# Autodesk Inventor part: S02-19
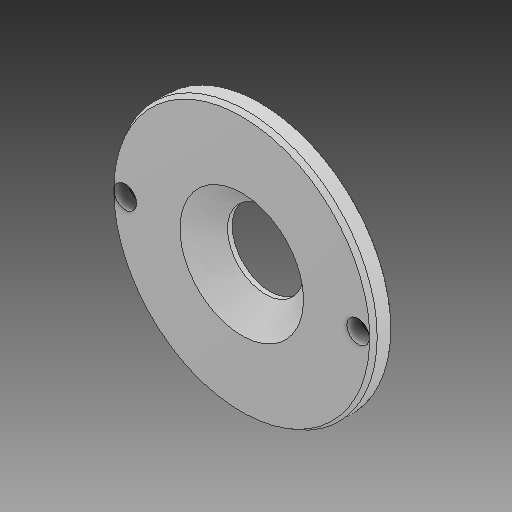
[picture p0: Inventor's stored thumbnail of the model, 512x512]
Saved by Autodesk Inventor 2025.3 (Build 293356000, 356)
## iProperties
Created: 2025-04
Part Number: S02-19
Material: Všeobecné
Document SubType Name: Modeling
Designer: Patrik
Density: 1 g/cm^3
Appearance: Výchozí
Description: Středící kroužek s osazením a konickým otvorem, s vývrty pro šrouby
Stock Number: E 1362_110_90_30x12
Mass: 84.3561 g
Surface Area: 219.333 cm^2
Volume: 84.3561 cm^3
User Status: 1.1730
Sending System: KiM GmbH
Major Version: 4.0
Minor Version: 0.0
Format Version: 0.0
Product Id: KiM GmbH
Hersteller: Meusburger
Material: 1.0503 (1.1730)
Bestellnummer: E 1362/110/90/30x12
Teilenummer: E 1362/110/90/30x12
Beschreibung: Zentrierflansch mit Ansatz und Bohrung konisch, Schraubenbohrungen _ Locating ring with neck, tapered bore and screw holes
cc_prop_force_one_body: 1
Author: Patrik
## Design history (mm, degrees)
feature "E 1362_110_90_30x12_1_1:1"
feature "Vyřezání1"
node "Těleso1"
feature "Plocha1"
node "Povrch1"
